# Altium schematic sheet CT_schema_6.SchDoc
size 254 x 245 mm
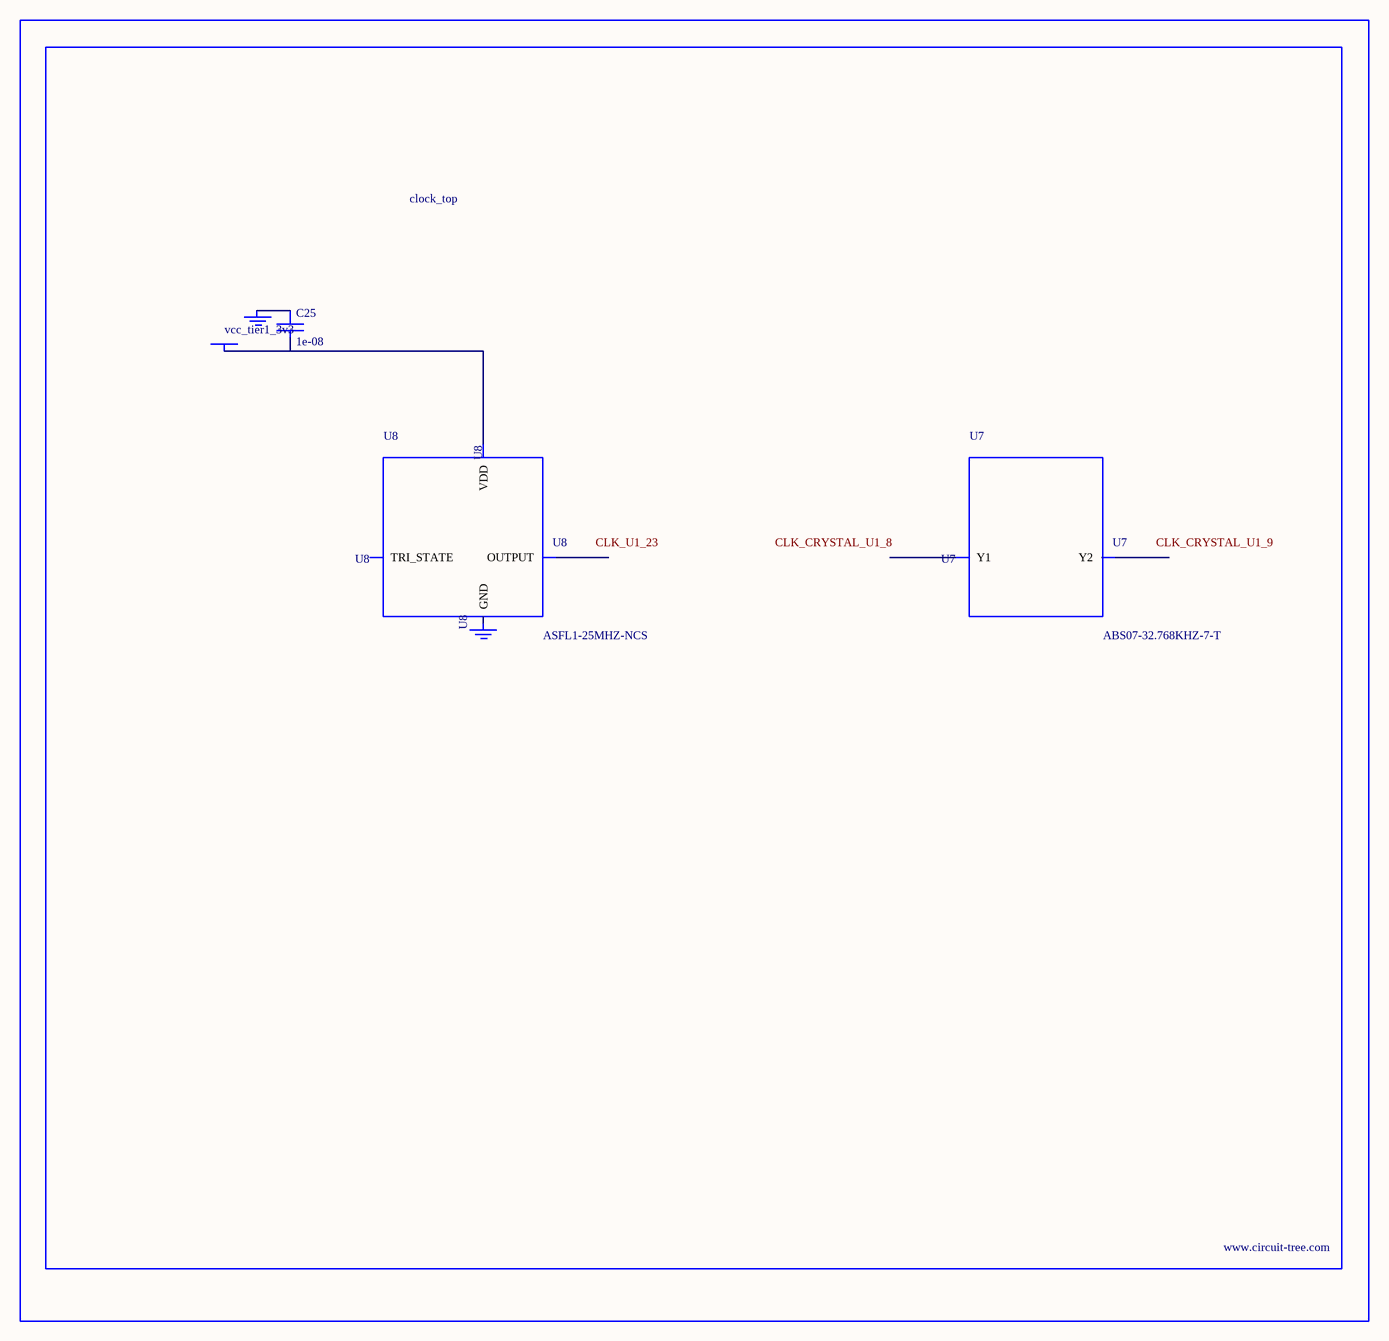
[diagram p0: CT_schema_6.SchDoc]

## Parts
BORDER5  (no value)
C25  1e-08  [C0402]
GND_INSTANCE_5_0  (no value)
GND_INSTANCE_5_1  (no value)
POWER_INSTANCE_5_0  vcc_tier1_3v3
U7  ABS07-32.768KHZ-7-T  [ABS07-32.768KHZ-7-T]
U8  ASFL1-25MHZ-NCS  [ASFL1]

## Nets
NetC25_1: C25.1 GND_INSTANCE_5_0.0(GND)
NetC25_2: C25.2 POWER_INSTANCE_5_0.0(PWR) U8.4(VDD)

Not connected (* = marked no-connect by the designer): GND_INSTANCE_5_1 0(GND); U7 1(Y1) 2(Y2); U8 1(TRI_STATE) 2(GND) 3(OUTPUT)

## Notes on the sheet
- Labels drawn without touching a wire or pin: CLK_CRYSTAL_U1_8, CLK_CRYSTAL_U1_9, CLK_U1_23

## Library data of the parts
BORDER5 = BORDER_PAGE5
C25 = C0402C103K3RAC
GND_INSTANCE_5_0 GND_INSTANCE_5_1 = GND
POWER_INSTANCE_5_0 = PWR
